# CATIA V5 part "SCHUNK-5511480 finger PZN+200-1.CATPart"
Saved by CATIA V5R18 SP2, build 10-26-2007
Part number: SCHUNK-5511480 finger PZN+200-1
Property "ParasolidId": 36
Property "PSOL_INSTNR": 1
Property "ParasolidId": 33
Property "PSOL_INSTNR": 2
Property "ParasolidId": 30
Property "PSOL_INSTNR": 3
Bounding box of the stored display mesh (mm): x -24.7 to 24.7, y 0 to 35.9, z 0 to 91
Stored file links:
  C:\Users\MIRCEA\Desktop\PRRO\CATIAV5\SCHUNK-5511480 finger PZN+200-1.CATPart
  C:\Program Files (x86)\Dassault Systemes\B21\intel_a\startup\materials\French\Catalog.CATMaterial
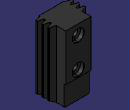
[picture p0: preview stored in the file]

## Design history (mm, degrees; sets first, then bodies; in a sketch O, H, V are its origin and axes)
Body1 "SCHUNK-5511480 finger PZN+200-1(1)" (main body)
  Solid1: solid without history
